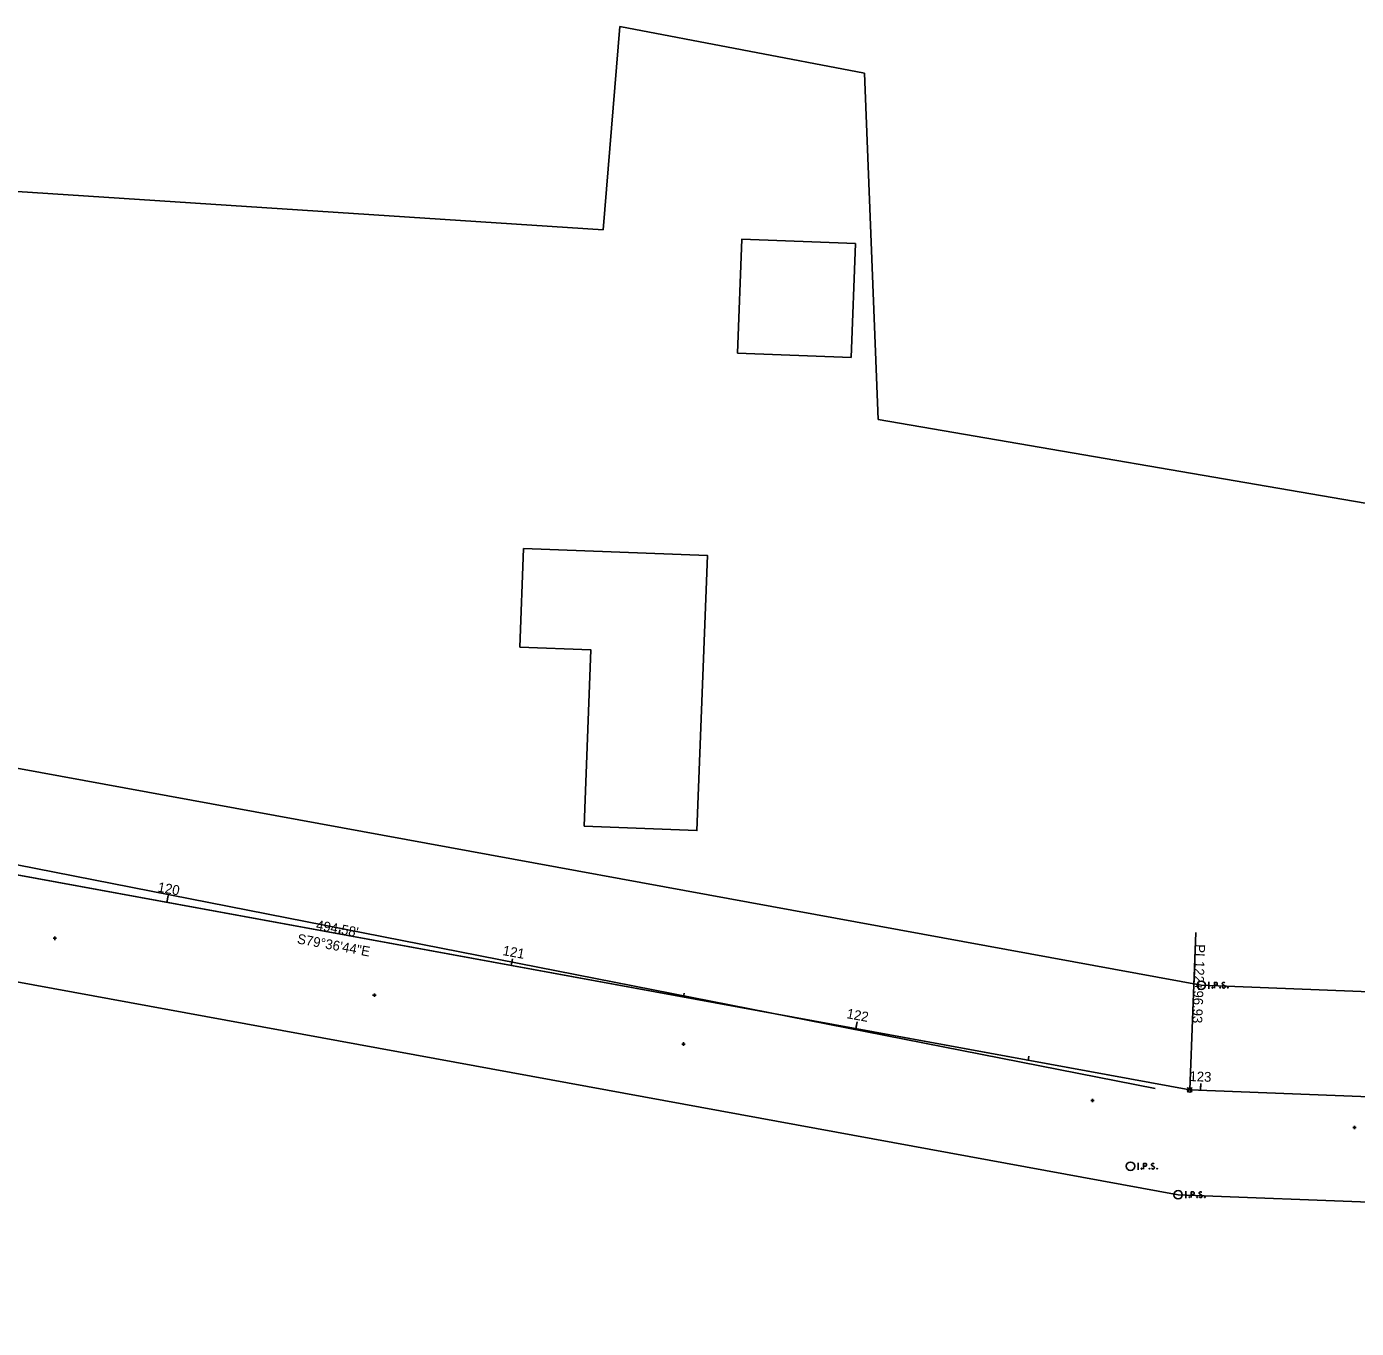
# Model space of a CAD drawing. Extents: x 2003596 to 2006933, y 570827 to 573780.
# Drawn here: x 2004699.4 to 2005079.1, y 572567.3 to 572938.9 of the extents above; entities that cross this region are included whole.
import ezdxf

# ---------------------------------------------------------------- set-up
doc = ezdxf.new("R2010")
doc.units = 0
for name, color, linetype in [('DT_X_Break_Line', 7, 'Continuous'), ('DV_X_Property_Line', 7, 'Continuous'), ('GE_X_Alignment', 7, 'Continuous'), ('GE_X_Alignment_1000_Bearings', 7, 'Continuous'), ('GE_X_Alignment_1000_Cardinal_Points', 7, 'Continuous'), ('GE_X_Alignment_1000_Distances', 7, 'Continuous'), ('GE_X_Alignment_1000_Stations', 7, 'Continuous'), ('GE_X_Alignment_100_Bearings', 7, 'Continuous'), ('GE_X_Alignment_100_Cardinal_Points', 7, 'Continuous'), ('GE_X_Alignment_100_Distances', 7, 'Continuous'), ('GE_X_Alignment_100_Stations', 7, 'Continuous'), ('GE_X_Alignment_500_Bearings', 7, 'Continuous'), ('GE_X_Alignment_500_Cardinal_Points', 7, 'Continuous'), ('GE_X_Alignment_500_Distances', 7, 'Continuous'), ('GE_X_Alignment_500_Stations', 7, 'Continuous'), ('RW_X_CL', 7, 'Continuous'), ('RW_X_Esmt_SH', 7, 'Continuous'), ('SC_Scratch1', 7, 'Continuous'), ('SC_Scratch8', 7, 'Continuous'), ('SV_P_Mon_Cells_Set', 7, 'Continuous'), ('SV_X_Random_Point', 7, 'Continuous'), ('SV_X_Shot_Marker', 7, 'Continuous')]:
    doc.layers.add(name, color=color, linetype=linetype)

msp = doc.modelspace()

# ---------------------------------------------------------------- linework, layer by layer
at = {"layer": 'DT_X_Break_Line'}
for points in [[(2004902.33, 572845.69), (2004903.58, 572878.16), (2004936.05, 572876.92), (2004934.8, 572844.45)], [(2004858.54, 572710.59), (2004860.48, 572760.97), (2004840.22, 572761.75), (2004841.3, 572789.89), (2004893.81, 572787.88), (2004890.8, 572709.36)]]:
    msp.add_lwpolyline(points, close=True, dxfattribs=at)
at = {"layer": 'DV_X_Property_Line'}
for p, q in [((2004864, 572880.82), (2004868.81, 572938.87)), ((2004868.81, 572938.87), (2004938.66, 572925.62)), ((2004938.66, 572925.62), (2004942.56, 572826.68)), ((2004666.28, 572893.76), (2004864, 572880.82)), ((2004942.56, 572826.68), (2005144.88, 572791.94))]:
    msp.add_line(p, q, dxfattribs=at)
at = {"layer": 'GE_X_Alignment'}
for p, q in [((2004545, 572724.5), (2005031.48, 572635.32)), ((2005031.48, 572635.32), (2006023.62, 572597.25))]:
    msp.add_line(p, q, dxfattribs=at)
at = {"layer": 'GE_X_Alignment_1000_Cardinal_Points'}
msp.add_line((2005031.48, 572635.32), (2005033.2, 572680.29), dxfattribs=at)
msp.add_circle((2005031.48, 572635.32), 0.6, dxfattribs=at)
at = {"layer": 'GE_X_Alignment_1000_Stations'}
msp.add_line((2004739.42, 572688.86), (2004739.78, 572690.83), dxfattribs=at)
at = {"layer": 'GE_X_Alignment_100_Cardinal_Points'}
msp.add_line((2005031.48, 572635.32), (2005033.2, 572680.29), dxfattribs=at)
msp.add_circle((2005031.48, 572635.32), 0.6, dxfattribs=at)
at = {"layer": 'GE_X_Alignment_100_Stations'}
for p, q in [((2004739.42, 572688.86), (2004739.78, 572690.83)), ((2004788.6, 572679.84), (2004788.81, 572681.02)), ((2004837.78, 572670.83), (2004838.14, 572672.79)), ((2004886.96, 572661.81), (2004887.18, 572662.99)), ((2004936.14, 572652.8), (2004936.5, 572654.76)), ((2004985.32, 572643.78), (2004985.54, 572644.96)), ((2005034.55, 572635.2), (2005034.63, 572637.2))]:
    msp.add_line(p, q, dxfattribs=at)
at = {"layer": 'GE_X_Alignment_500_Cardinal_Points'}
msp.add_line((2005031.48, 572635.32), (2005033.2, 572680.29), dxfattribs=at)
msp.add_circle((2005031.48, 572635.32), 0.6, dxfattribs=at)
at = {"layer": 'GE_X_Alignment_500_Stations'}
for p, q in [((2004739.42, 572688.86), (2004739.78, 572690.83)), ((2004837.78, 572670.83), (2004837.99, 572672.01)), ((2004936.14, 572652.8), (2004936.36, 572653.98)), ((2005034.55, 572635.2), (2005034.59, 572636.4))]:
    msp.add_line(p, q, dxfattribs=at)
at = {"layer": 'RW_X_CL'}
for p, q in [((2005031.48, 572635.32), (2004545, 572724.5)), ((2006023.62, 572597.25), (2005031.48, 572635.32))]:
    msp.add_line(p, q, dxfattribs=at)
at = {"layer": 'RW_X_Esmt_SH'}
for p, q in [((2004550.41, 572754.01), (2005034.78, 572665.22)), ((2004539.59, 572694.99), (2005028.18, 572605.42)), ((2005034.78, 572665.22), (2006024.45, 572627.24)), ((2005028.18, 572605.42), (2006022.8, 572567.26))]:
    msp.add_line(p, q, dxfattribs=at)
at = {"layer": 'SC_Scratch1'}
msp.add_line((2004433.11, 572745.04), (2005031.48, 572635.32), dxfattribs=at)
at = {"layer": 'SC_Scratch8'}
msp.add_line((2005021.66, 572635.7), (2004450.87, 572747.83), dxfattribs=at)
at = {"layer": 'SV_P_Mon_Cells_Set'}
for points in [[(2005036.79, 572666.02), (2005037.15, 572666.02)], [(2005036.79, 572664.42), (2005037.15, 572664.42)], [(2005036.97, 572664.42), (2005036.97, 572666.02)], [(2005037.93, 572664.63), (2005037.98, 572664.63), (2005038.02, 572664.61), (2005038.05, 572664.56), (2005038.05, 572664.49), (2005038.02, 572664.44), (2005037.98, 572664.42), (2005037.93, 572664.42), (2005037.9, 572664.44), (2005037.86, 572664.49), (2005037.86, 572664.56), (2005037.9, 572664.61), (2005037.93, 572664.63)], [(2005038.54, 572664.42), (2005038.54, 572666.02), (2005039.06, 572666.02), (2005039.12, 572666), (2005039.2, 572665.98), (2005039.23, 572665.95), (2005039.26, 572665.93), (2005039.31, 572665.87), (2005039.34, 572665.8), (2005039.36, 572665.7), (2005039.36, 572665.55), (2005039.35, 572665.5), (2005039.33, 572665.42), (2005039.29, 572665.34), (2005039.24, 572665.3), (2005039.21, 572665.27), (2005039.15, 572665.25), (2005039.06, 572665.24), (2005038.54, 572665.24)], [(2005040.18, 572664.63), (2005040.23, 572664.63), (2005040.27, 572664.61), (2005040.3, 572664.56), (2005040.3, 572664.49), (2005040.27, 572664.44), (2005040.23, 572664.42), (2005040.18, 572664.42), (2005040.15, 572664.44), (2005040.11, 572664.49), (2005040.11, 572664.56), (2005040.15, 572664.61), (2005040.18, 572664.63)], [(2005041.55, 572665.9), (2005041.52, 572665.93), (2005041.49, 572665.95), (2005041.39, 572665.99), (2005041.27, 572666.02), (2005041.18, 572666.02), (2005041.15, 572666.02), (2005041, 572665.98), (2005040.88, 572665.9), (2005040.81, 572665.8), (2005040.78, 572665.7), (2005040.78, 572665.63), (2005040.81, 572665.53), (2005040.89, 572665.44), (2005041.5, 572665.06), (2005041.56, 572665.01), (2005041.58, 572664.96), (2005041.6, 572664.88), (2005041.6, 572664.81), (2005041.59, 572664.73), (2005041.58, 572664.68), (2005041.56, 572664.62), (2005041.53, 572664.57), (2005041.51, 572664.53), (2005041.48, 572664.49), (2005041.45, 572664.47), (2005041.4, 572664.44), (2005041.37, 572664.43), (2005041.27, 572664.42), (2005041.12, 572664.42), (2005041.02, 572664.44), (2005040.87, 572664.53), (2005040.78, 572664.61)], [(2005042.36, 572664.63), (2005042.42, 572664.63), (2005042.45, 572664.61), (2005042.48, 572664.56), (2005042.48, 572664.49), (2005042.45, 572664.44), (2005042.42, 572664.42), (2005042.36, 572664.42), (2005042.33, 572664.44), (2005042.29, 572664.49), (2005042.29, 572664.56), (2005042.33, 572664.61), (2005042.36, 572664.63)], [(2005016.59, 572614.35), (2005016.95, 572614.35)], [(2005016.59, 572612.75), (2005016.95, 572612.75)], [(2005016.77, 572612.75), (2005016.77, 572614.35)], [(2005017.73, 572612.97), (2005017.79, 572612.97), (2005017.82, 572612.94), (2005017.85, 572612.89), (2005017.85, 572612.83), (2005017.82, 572612.78), (2005017.79, 572612.75), (2005017.73, 572612.75), (2005017.7, 572612.78), (2005017.66, 572612.83), (2005017.66, 572612.89), (2005017.7, 572612.94), (2005017.73, 572612.97)], [(2005018.34, 572612.75), (2005018.34, 572614.35), (2005018.87, 572614.35), (2005018.92, 572614.34), (2005019, 572614.32), (2005019.03, 572614.29), (2005019.06, 572614.27), (2005019.11, 572614.2), (2005019.14, 572614.14), (2005019.16, 572614.04), (2005019.16, 572613.89), (2005019.15, 572613.84), (2005019.13, 572613.76), (2005019.09, 572613.67), (2005019.04, 572613.64), (2005019.01, 572613.61), (2005018.95, 572613.59), (2005018.87, 572613.57), (2005018.34, 572613.57)], [(2005019.98, 572612.97), (2005020.03, 572612.97), (2005020.07, 572612.94), (2005020.1, 572612.89), (2005020.1, 572612.83), (2005020.07, 572612.78), (2005020.03, 572612.75), (2005019.98, 572612.75), (2005019.95, 572612.78), (2005019.91, 572612.83), (2005019.91, 572612.89), (2005019.95, 572612.94), (2005019.98, 572612.97)], [(2005021.35, 572614.24), (2005021.32, 572614.27), (2005021.29, 572614.29), (2005021.19, 572614.33), (2005021.07, 572614.35), (2005020.98, 572614.35), (2005020.95, 572614.35), (2005020.81, 572614.32), (2005020.68, 572614.24), (2005020.61, 572614.14), (2005020.59, 572614.04), (2005020.59, 572613.96), (2005020.61, 572613.86), (2005020.7, 572613.78), (2005021.3, 572613.4), (2005021.36, 572613.35), (2005021.38, 572613.3), (2005021.4, 572613.22), (2005021.4, 572613.15), (2005021.39, 572613.07), (2005021.38, 572613.02), (2005021.36, 572612.96), (2005021.33, 572612.91), (2005021.31, 572612.87), (2005021.28, 572612.83), (2005021.25, 572612.81), (2005021.2, 572612.78), (2005021.17, 572612.77), (2005021.07, 572612.75), (2005020.92, 572612.75), (2005020.82, 572612.78), (2005020.67, 572612.87), (2005020.59, 572612.94)], [(2005022.16, 572612.97), (2005022.22, 572612.97), (2005022.25, 572612.94), (2005022.28, 572612.89), (2005022.28, 572612.83), (2005022.25, 572612.78), (2005022.22, 572612.75), (2005022.16, 572612.75), (2005022.13, 572612.78), (2005022.1, 572612.83), (2005022.1, 572612.89), (2005022.13, 572612.94), (2005022.16, 572612.97)], [(2005030.2, 572606.23), (2005030.55, 572606.23)], [(2005030.2, 572604.63), (2005030.55, 572604.63)], [(2005030.38, 572604.63), (2005030.38, 572606.23)], [(2005031.34, 572604.84), (2005031.39, 572604.84), (2005031.42, 572604.81), (2005031.46, 572604.76), (2005031.46, 572604.7), (2005031.42, 572604.65), (2005031.39, 572604.63), (2005031.34, 572604.63), (2005031.3, 572604.65), (2005031.27, 572604.7), (2005031.27, 572604.76), (2005031.3, 572604.81), (2005031.34, 572604.84)], [(2005031.94, 572604.63), (2005031.94, 572606.23), (2005032.47, 572606.23), (2005032.53, 572606.21), (2005032.6, 572606.19), (2005032.64, 572606.16), (2005032.67, 572606.14), (2005032.71, 572606.07), (2005032.75, 572606.01), (2005032.77, 572605.91), (2005032.77, 572605.76), (2005032.76, 572605.71), (2005032.74, 572605.63), (2005032.69, 572605.55), (2005032.65, 572605.51), (2005032.62, 572605.48), (2005032.56, 572605.46), (2005032.47, 572605.44), (2005031.94, 572605.44)], [(2005033.59, 572604.84), (2005033.64, 572604.84), (2005033.67, 572604.81), (2005033.71, 572604.76), (2005033.71, 572604.7), (2005033.67, 572604.65), (2005033.64, 572604.63), (2005033.59, 572604.63), (2005033.55, 572604.65), (2005033.52, 572604.7), (2005033.52, 572604.76), (2005033.55, 572604.81), (2005033.59, 572604.84)], [(2005034.95, 572606.11), (2005034.93, 572606.14), (2005034.9, 572606.16), (2005034.8, 572606.2), (2005034.68, 572606.23), (2005034.59, 572606.23), (2005034.56, 572606.23), (2005034.41, 572606.19), (2005034.29, 572606.11), (2005034.21, 572606.01), (2005034.19, 572605.91), (2005034.19, 572605.84), (2005034.21, 572605.73), (2005034.3, 572605.65), (2005034.91, 572605.27), (2005034.96, 572605.22), (2005034.98, 572605.17), (2005035.01, 572605.09), (2005035.01, 572605.02), (2005035, 572604.94), (2005034.98, 572604.89), (2005034.96, 572604.83), (2005034.94, 572604.78), (2005034.92, 572604.74), (2005034.89, 572604.7), (2005034.85, 572604.68), (2005034.81, 572604.65), (2005034.78, 572604.64), (2005034.68, 572604.63), (2005034.52, 572604.63), (2005034.42, 572604.65), (2005034.28, 572604.74), (2005034.19, 572604.81)], [(2005035.77, 572604.84), (2005035.82, 572604.84), (2005035.86, 572604.81), (2005035.89, 572604.76), (2005035.89, 572604.7), (2005035.86, 572604.65), (2005035.82, 572604.63), (2005035.77, 572604.63), (2005035.73, 572604.65), (2005035.7, 572604.7), (2005035.7, 572604.76), (2005035.73, 572604.81), (2005035.77, 572604.84)]]:
    msp.add_lwpolyline(points, dxfattribs=at)
for centre in [(2005034.78, 572665.22), (2005014.58, 572613.55), (2005028.18, 572605.42)]:
    msp.add_circle(centre, 1.2, dxfattribs=at)
at = {"layer": 'SV_X_Random_Point'}
for p, q in [((2005030.81, 572634.65), (2005032.15, 572635.99)), ((2005030.81, 572635.99), (2005032.15, 572634.65))]:
    msp.add_line(p, q, dxfattribs=at)
at = {"layer": 'SV_X_Shot_Marker'}
for p, q in [((2004706.95, 572678.62), (2004707.95, 572678.62)), ((2004707.45, 572679.12), (2004707.45, 572678.12)), ((2004707.45, 572678.62), (2004707.45, 572678.62)), ((2004798.19, 572662.37), (2004799.19, 572662.37)), ((2004798.69, 572662.87), (2004798.69, 572661.87)), ((2004798.69, 572662.37), (2004798.69, 572662.37)), ((2004886.45, 572648.44), (2004887.45, 572648.44)), ((2004886.95, 572648.94), (2004886.95, 572647.94)), ((2004886.95, 572648.44), (2004886.95, 572648.44)), ((2005003.23, 572632.3), (2005004.23, 572632.3)), ((2005003.73, 572632.8), (2005003.73, 572631.8)), ((2005003.73, 572632.3), (2005003.73, 572632.3)), ((2005078.02, 572624.61), (2005079.02, 572624.61)), ((2005078.52, 572625.11), (2005078.52, 572624.11)), ((2005078.52, 572624.61), (2005078.52, 572624.61))]:
    msp.add_line(p, q, dxfattribs=at)

# ---------------------------------------------------------------- texts
at = {"layer": 'GE_X_Alignment_1000_Bearings'}
msp.add_text('S79°36\'44"E', height=2.8, rotation=349.6122, dxfattribs=at).set_placement((2004776.48, 572677.18))
at = {"layer": 'GE_X_Alignment_1000_Cardinal_Points'}
for s, p in [('PI', (2005033.12, 572676.98)), ('122+96.93', (2005032.94, 572672.2))]:
    msp.add_text(s, height=2.8, rotation=267.8026, dxfattribs=at).set_placement(p)
at = {"layer": 'GE_X_Alignment_1000_Distances'}
msp.add_text("494.58'", height=2.8, rotation=349.6122, dxfattribs=at).set_placement((2004781.87, 572681.12))
at = {"layer": 'GE_X_Alignment_1000_Stations'}
msp.add_text('120', height=2.8, rotation=349.6122, dxfattribs=at).set_placement((2004736.65, 572691.96))
at = {"layer": 'GE_X_Alignment_100_Bearings'}
msp.add_text('S79°36\'44"E', height=2.8, rotation=349.6122, dxfattribs=at).set_placement((2004776.48, 572677.18))
at = {"layer": 'GE_X_Alignment_100_Cardinal_Points'}
for s, p in [('PI', (2005033.12, 572676.98)), ('122+96.93', (2005032.94, 572672.2))]:
    msp.add_text(s, height=2.8, rotation=267.8026, dxfattribs=at).set_placement(p)
at = {"layer": 'GE_X_Alignment_100_Distances'}
msp.add_text("494.58'", height=2.8, rotation=349.6122, dxfattribs=at).set_placement((2004781.87, 572681.12))
at = {"layer": 'GE_X_Alignment_100_Stations'}
for s, rotation, p in [('120', 349.6122, (2004736.65, 572691.96)), ('121', 349.6122, (2004835.17, 572673.85)), ('122', 349.6122, (2004933.37, 572655.85)), ('123', 357.8026, (2005031.38, 572637.87))]:
    msp.add_text(s, height=2.8, rotation=rotation, dxfattribs=at).set_placement(p)
at = {"layer": 'GE_X_Alignment_500_Bearings'}
msp.add_text('S79°36\'44"E', height=2.8, rotation=349.6122, dxfattribs=at).set_placement((2004776.48, 572677.18))
at = {"layer": 'GE_X_Alignment_500_Cardinal_Points'}
for s, p in [('PI', (2005033.12, 572676.98)), ('122+96.93', (2005032.94, 572672.2))]:
    msp.add_text(s, height=2.8, rotation=267.8026, dxfattribs=at).set_placement(p)
at = {"layer": 'GE_X_Alignment_500_Distances'}
msp.add_text("494.58'", height=2.8, rotation=349.6122, dxfattribs=at).set_placement((2004781.87, 572681.12))
at = {"layer": 'GE_X_Alignment_500_Stations'}
msp.add_text('120', height=2.8, rotation=349.6122, dxfattribs=at).set_placement((2004736.65, 572691.96))

doc.saveas('drawing.dxf')
